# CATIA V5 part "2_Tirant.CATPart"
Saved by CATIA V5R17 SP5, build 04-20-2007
Part number: 2_Tirant
Bounding box of the stored display mesh (mm): x -5.91 to 5.91, y -150 to 0, z -5.992 to 5.992
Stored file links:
  C:\Users\Frédéric\Documents\WF\STSCPI 09-11\Projets\Projet multiplicateur eolienne\Maquette eolienne\2_Tirant.CATPart
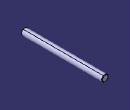
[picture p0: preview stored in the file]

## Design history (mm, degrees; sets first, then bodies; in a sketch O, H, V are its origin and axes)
AxisSystem1: origin (0, 0, 0), X (1, 0, 0), Y (0, 1, 0), Z (0, 0, 1)
Body1 (main body)
  Sketch1 on YZ plane of AxisSystem1, origin (0, 0, 0), H (0, 1, 0), V (0, 0, 1)
    line L1 (0, 0) -> (-150, 0)
    line L2 (-150, 0) -> (-150, 6)
    line L3 (-150, 6) -> (0, 6)
    line L4 (0, 6) -> (0, 0)
    length L4 = 6
    length L3 = 150
    horizontal: L1 H, L3 H
    vertical: L2 V, L4 V
  Shaft1: profile Sketch1, axis Sketch1.L1, angle 360
  Chamfer1: length 1, angle 45, on edge [face of Shaft1 from Sketch1.L3 | face of Shaft1 from Sketch1.L4]
  Thread1: "M12", diameter 12, depth 32, pitch 1.75, on face of Shaft1 from Sketch1.L3, from face of Shaft1 from Sketch1.L4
